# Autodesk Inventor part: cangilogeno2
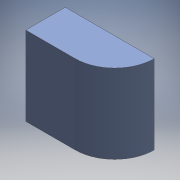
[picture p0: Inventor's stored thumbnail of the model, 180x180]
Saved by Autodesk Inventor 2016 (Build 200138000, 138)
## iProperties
Created: 2016-06
Part Number: cangilogeno2
Material: Genérico
Document SubType Name: Modeling
Designer: adm
Density: 1 g/cm^3
Appearance: Valor por defecto
Author: adm
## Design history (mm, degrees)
sketch "Boceto1"
  geometry: L1 (22.5, 10)-(-22.5, 10); L2 (-22.5, 10)-(-22.5, -10); L3 (-22.5, -10)-(2.5, -10); L4 (22.5, 10)-(22.5, 10); A1 r 20 centre (2.5, 10) between (2.5, -10) and (22.5, 10); 1 further point
  constraints: 8 end point, 2 parallel, 2 point on circle, 2 tangent, 1 centre point, 1 horizontal, 1 perpendicular
  dimensions: "d1" = 20 distance of L2.end L1.end; "d2" = 20 radius of A1
extrude "Extrusión1" new body sketch "Boceto1" distance "d3" = 40; taper "d4" = 0 deg
feature "Vaciado1" dims "d5" = 3
node "Sólido1"
